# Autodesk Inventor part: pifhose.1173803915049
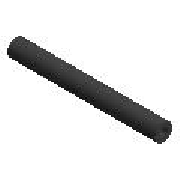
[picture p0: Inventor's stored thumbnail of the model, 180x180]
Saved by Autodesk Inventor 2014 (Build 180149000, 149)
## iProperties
NAME: PIPING: Parker Hydraulic Hose - No Skive
DATA: <meta><inlinegroups number="1" deflen="12.7"></inlinegroups><connections number="2"></connections><angles><a>3.14159265358979</a></angles></meta>
Company: Autodesk, Inc.
Created: 2007-02
Material: Rubber
Description: Hose
Document SubType Name: Modeling
Standard: Parker
Designer: Autodesk, Inc.
Manufacturer: Parker
Language: en-US
Size Designation: 1/2 - 5
Categories: <MemberInstance><Categories><Category DisplayName="Tube &amp; Pipe" InternalName="4347fa0f-2144-441d-94cd-e3e15c92b736" Mnemonic="TUBEANDPIPE"><CategoryParamete
Stock Number: Parker Hydraulic Hose - No Skive 1/2
Density: 1 g/cm^3
Appearance: Rubber (Black)
L: 45.614 in
PL: 45.614 in
RPL: 45.625 in
OPL: 48.014 in
ROPL: 48.125 in
Author: Autodesk, Inc.
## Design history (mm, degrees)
sketch "3D Sketch1" dims "d4" = 10, "d5" = 10
workpoint "Work Point3"
workpoint "Work Point4"
workplane "Work Plane1"
sketch "Sketch2"
  geometry: C1 r 11.176 at (0, 0); C2 r 6.35 at (0, 0); 1 further point
  constraints: 2 centre point
workpoint "Work Point5"
sweep "Sweep1" dims "d6" = 0
body "Solid1"
other parameters: "ID" = 12.7 [user parameter], "OD" = 22.352 [user parameter], "L" = 1158.5956 (= PL) [user parameter], "PL" = 1158.5956 [user parameter; used in 1 equation term], "Size_Designation" = 5 [user parameter], "RPL" = 1158.875 [user parameter], "OPL" = 1219.5556 [user parameter], "ROPL" = 1222.375 [user parameter]
